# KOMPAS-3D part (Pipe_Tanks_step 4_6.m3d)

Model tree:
1. X Axis
2. Y Axis
3. Z Axis  (labels: Pipe Dn 150)
     Òîëùèíà ñòåíêè 1 = 1

Referenced files in C:\Documents and Settings\kashirsky\Мои документы\Camtasia Studio\Pipelines3D\Tanks\: Tanks_step 4.a3d
Referenced files in C:\Program Files\ASCON\KOMPAS-3D V10\Libs\Piping\LOAD\: Piping_C_Pipe_150_1000.m3d
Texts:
  Pipe Dn 150
  Steel ASTM A295
  Three Point Plane
  Plane at Angle
  Line and Point Plane
  Axis through Two Vertices
  Axis of Feature
  Axis of Conical Surface
  Axis through Edge
  Trim by Surface
  Trim by Sketch
  Feature with No History
  Intersection Axis of Two Planes
  Two Line Plane
  Line and Face Plane
  Bend by line
  Hole in sheet body
  Cut in sheet body
  Point in CM
  Linear Dimension from Line to Point
  Surface Finish Symbol
  Geometric Tolerance Symbol
  Leader #1
  Leader #2
  Leader #3
  Shape Deviations and Datum
  Node point number
  Mark of coordination axis
  Node point designation
  Mark/Reference designation with leader
  Mark/reference designation on line
  Mark/Reference designation without leader
  Plane of section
